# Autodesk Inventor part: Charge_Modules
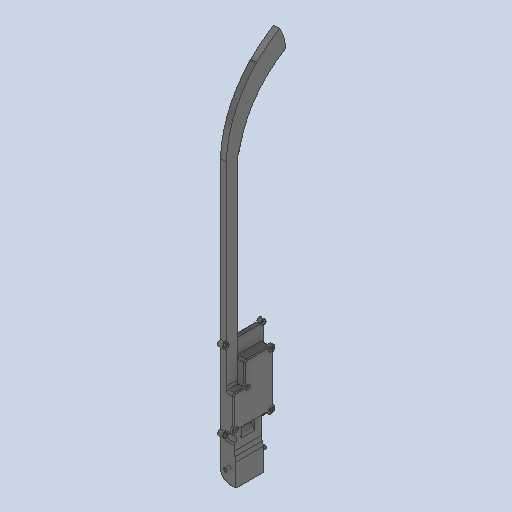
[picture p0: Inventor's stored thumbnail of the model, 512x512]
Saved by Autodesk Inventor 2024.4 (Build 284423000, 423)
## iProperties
Created: 2025-05
Part Number: Charge_Modules
Material: Generic
Document SubType Name: Modeling
Designer: AdminForWorker
Density: 1 g/cm^3
Appearance: Default
Title: Charge_Modules
Author: AdminForWorker
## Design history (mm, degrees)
feature "Body2"
feature "Body3"
body "Solid1"
body "Solid2"
